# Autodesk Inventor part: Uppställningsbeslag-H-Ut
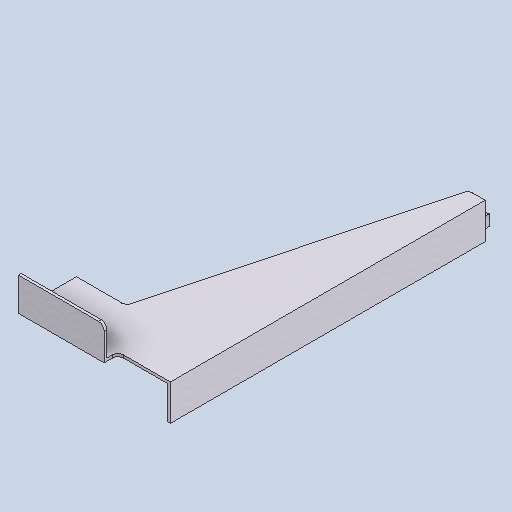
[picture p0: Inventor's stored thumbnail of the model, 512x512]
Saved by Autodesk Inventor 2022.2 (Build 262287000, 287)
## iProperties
Created: 2019-06
Part Number: Uppställningsbeslag-H-Ut
Material: Aluminum 6061, Welded
Document SubType Name: Modeling
Designer: cl
Density: 2.7 g/cm^3
Appearance: Weld - Aluminum
Author: cl
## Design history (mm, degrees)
sketch "Sketch1"
  geometry: L1 (95, 25)-(250, 25); L2 (250, 25)-(250, -80); L3 (250, -80)-(167.693, -80); L4 (0, 0)-(0, -570); L5 (0, -570)-(22.307, -570); L6 (31.973, -562.564)-(158.027, -87.436); L7 (95, 25)-(95, 10); L8 (85, 0)-(0, 0); A1 r 10 centre (167.693, -90) between (167.693, -80) and (158.027, -87.436); A2 r 10 centre (22.307, -560) between (22.307, -570) and (31.973, -562.564); A3 r 10 centre (85, 10) between (85, 0) and (95, 10); 4 further points
  constraints: 16 end point, 6 point on circle, 6 point on line, 6 tangent, 4 perpendicular, 3 centre point, 2 vertical, 1 coincident, 1 equal radius, 1 horizontal
  dimensions: "d1" = 105 distance of L1.end L2.end; "d3" = 90 distance of L2.end point (160, -80); "d4" = 570 distance of point (0, 0) L4.end; "d5" = 30 distance of L4.end point (30, -570); "d6" = 10 radius of A1; "d7" = 25 distance of L1.start point (95, 0); "d8" = 95 distance of L4.start point (95, 0); "d9" = 250 distance between parallel lines of L2 L4; "d10" = 10 radius of A3
extrude "Extrusion1" new body sketch "Sketch1" distance "d11" = 5; taper "d12" = 0 deg
sketch "Sketch2"
  geometry: L1 (-250, -25)-(-95, -25); L2 (-95, -25)-(-95, -20); L3 (-95, -20)-(-250, -20); L4 (-250, -20)-(-250, -25); L5 (-250, -25)-(-95, -25) reference; L6 (-250, 80)-(-250, -25) reference; L7 (-95, -25)-(-95, -10) reference; 1 further point
  constraints: 8 end point, 3 collinear, 2 parallel, 1 horizontal, 1 perpendicular
  dimensions: "d13" = 5 distance of L3.end L1.start
extrude "Extrusion2" join sketch "Sketch2" distance "d14" = 55; taper "d15" = 0 deg
fillet "Fillet1" dims "d16" = 10
sketch "Sketch3"
  geometry: L1 (0, 0)-(-5, 0); L2 (-5, 0)-(-5, -570); L3 (-5, -570)-(0, -570); L4 (0, -570)-(0, 0); L5 (0, 0)-(0, -570) reference; L6 (0, -570)-(-22.307, -570) reference; L7 (-85, 0)-(0, 0) reference
  constraints: 8 end point, 3 collinear, 2 parallel, 1 horizontal, 1 perpendicular
  dimensions: "d17" = 5 distance of L1.start L1.end
extrude "Extrusion3" join sketch "Sketch3" distance "d18" = 60; taper "d19" = 0 deg
sketch "Sketch4"
  geometry: L1 (5, -5)-(5, -65) reference; L2 (5, -30)-(25, -30); L3 (25, -30)-(25, -55); L4 (25, -55)-(5, -55); L5 (5, -55)-(5, -30); L6 (5, -5)-(22.307, -5) reference; 1 further point
  constraints: 8 end point, 2 parallel, 1 horizontal, 1 perpendicular, 1 point on line
  dimensions: "d20" = 25 distance of L2.end L3.end; "d21" = 20 distance of L2.start L2.end; "d22" = 25 distance between parallel lines of L6 L2
extrude "Extrusion4" join sketch "Sketch4" distance "d23" = 80; taper "d24" = 0 deg
sketch "Sketch5"
  geometry: L1 (22.5, -32.5)-(7.5, -32.5); L2 (7.5, -32.5)-(7.5, -52.5); L3 (7.5, -52.5)-(22.5, -52.5); L4 (22.5, -52.5)-(22.5, -32.5); L5 (25, -30)-(5, -30) reference; L6 (25, -55)-(25, -30) reference; 1 further point
  constraints: 8 end point, 2 parallel, 1 horizontal, 1 perpendicular
  dimensions: "d25" = 15 distance of L1.start L1.end; "d26" = 20 distance of L3.end L1.start; "d27" = 2.5 distance between parallel lines of L5 L1; "d28" = 2.5 distance between parallel lines of L4 L6
extrude "Extrusion5" join sketch "Sketch5" distance "d29" = 15; taper "d30" = 0 deg
fillet "Fillet2" dims "d31" = 15
body "Solid1"
